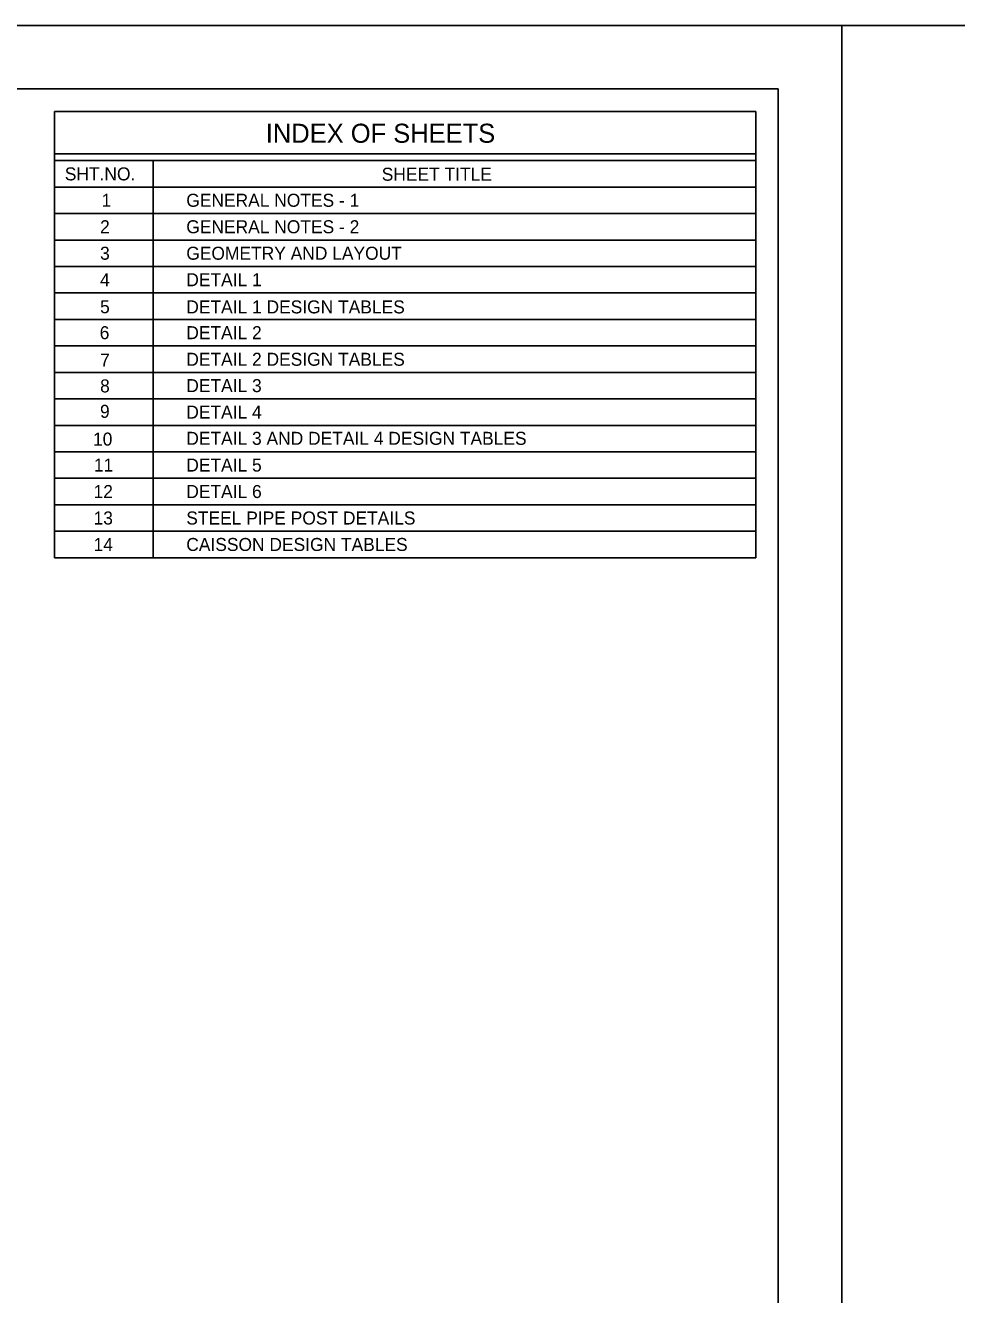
# Model space of a CAD drawing. Extents: x 3475 to 6558, y -3780 to 1166.
# Drawn here: x 4409.6 to 4629.5, y 866.1 to 1165.7 of the extents above; entities that cross this region are included whole.
import ezdxf

# ---------------------------------------------------------------- set-up
doc = ezdxf.new("R2010")
doc.units = 0
for name, color, linetype in [('1', 7, 'Continuous'), ('2', 7, 'Continuous'), ('PLT-BNDY', 7, 'Continuous')]:
    doc.layers.add(name, color=color, linetype=linetype)

msp = doc.modelspace()

# ---------------------------------------------------------------- linework, layer by layer
at = {"layer": '1'}
for p, q in [((4582.01, 1145.36), (4416.44, 1145.36)), ((4416.44, 1040.03), (4416.44, 1145.36)), ((4582.01, 1040.03), (4582.01, 1145.36)), ((4582.01, 1135.36), (4416.44, 1135.36)), ((4582.01, 1133.78), (4416.44, 1133.78)), ((4439.71, 1040.03), (4439.71, 1133.84)), ((4582.01, 1127.53), (4416.44, 1127.53)), ((4582.01, 1121.28), (4416.44, 1121.28)), ((4582.01, 1115.03), (4416.44, 1115.03)), ((4582.01, 1108.78), (4416.44, 1108.78)), ((4582.01, 1102.53), (4416.44, 1102.53)), ((4582.01, 1096.28), (4416.44, 1096.28)), ((4582.01, 1090.03), (4416.44, 1090.03)), ((4582.01, 1083.78), (4416.44, 1083.78)), ((4582.01, 1077.53), (4416.44, 1077.53)), ((4582.01, 1071.28), (4416.44, 1071.28)), ((4582.01, 1065.03), (4416.44, 1065.03)), ((4582.01, 1058.78), (4416.44, 1058.78)), ((4582.01, 1052.53), (4416.44, 1052.53)), ((4582.01, 1046.28), (4416.44, 1046.28)), ((4582.01, 1040.03), (4416.44, 1040.03))]:
    msp.add_line(p, q, dxfattribs=at)
at = {"layer": '2'}
for p, q in [((3801.34, 1150.69), (4587.34, 1150.69)), ((4587.34, 1150.69), (4587.34, 586.69))]:
    msp.add_line(p, q, dxfattribs=at)
at = {"layer": 'PLT-BNDY'}
for points in [[(3761.34, 1165.69), (4602.34, 1165.69), (4602.34, 571.69), (3761.34, 571.69)], [(4602.34, 1165.69), (5443.34, 1165.69), (5443.34, 571.69), (4602.34, 571.69)]]:
    msp.add_lwpolyline(points, close=True, dxfattribs=at)

# ---------------------------------------------------------------- texts
at = {"layer": '1'}
for s, height, p in [('INDEX OF SHEETS', 4.5001, (4466.34, 1137.98)), ('SHT.NO.', 3.072, (4418.87, 1129.1)), ('SHEET TITLE', 3.072, (4493.71, 1129.02)), ('1', 3.07, (4427.56, 1122.87)), ('GENERAL NOTES - 1', 3.072, (4447.56, 1122.87)), ('2', 3.07, (4427.21, 1116.62)), ('GENERAL NOTES - 2', 3.072, (4447.56, 1116.62)), ('3', 3.07, (4427.21, 1110.37)), ('GEOMETRY AND LAYOUT', 3.072, (4447.56, 1110.37)), ('4', 3.07, (4427.21, 1104.12)), ('DETAIL 1', 3.072, (4447.56, 1104.12)), ('5', 3.07, (4427.21, 1097.75)), ('DETAIL 1 DESIGN TABLES', 3.072, (4447.56, 1097.7)), ('6', 3.07, (4427.12, 1091.62)), ('DETAIL 2', 3.072, (4447.56, 1091.62)), ('7', 3.07, (4427.21, 1085.13)), ('DETAIL 2 DESIGN TABLES', 3.072, (4447.56, 1085.34)), ('8', 3.07, (4427.21, 1079.06)), ('DETAIL 3', 3.072, (4447.56, 1079.12)), ('9', 3.07, (4427.19, 1073.05)), ('DETAIL 4', 3.072, (4447.56, 1072.87)), ('10', 3.072, (4425.54, 1066.5)), ('DETAIL 3 AND DETAIL 4 DESIGN TABLES', 3.072, (4447.56, 1066.68)), ('11', 3.072, (4425.74, 1060.37)), ('DETAIL 5', 3.072, (4447.56, 1060.37)), ('12', 3.072, (4425.67, 1054.12)), ('DETAIL 6', 3.072, (4447.56, 1054.12)), ('13', 3.072, (4425.67, 1047.87)), ('STEEL PIPE POST DETAILS', 3.072, (4447.56, 1047.87)), ('14', 3.072, (4425.67, 1041.62)), ('CAISSON DESIGN TABLES', 3.072, (4447.56, 1041.62))]:
    msp.add_text(s, height=height, dxfattribs=at).set_placement(p)

doc.saveas('drawing.dxf')
